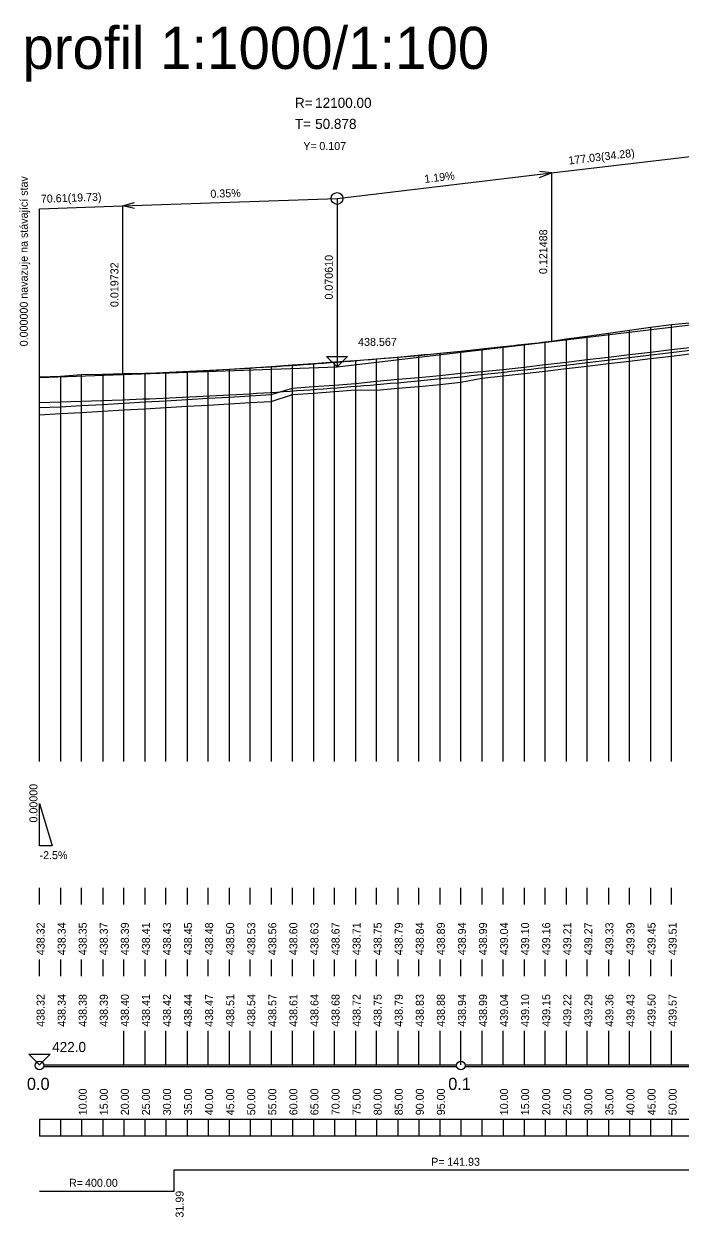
# Model space of a CAD drawing. Extents: x -240 to 1040, y 276 to 593.
# Drawn here: x 1.3 to 157, y 295.8 to 579.1 of the extents above; entities that cross this region are included whole.
import ezdxf

# ---------------------------------------------------------------- set-up
doc = ezdxf.new("R2010")
doc.units = 0
for name, color, linetype in [('1', 7, 'Continuous'), ('2', 7, 'Continuous'), ('FORMATY', 7, 'Continuous')]:
    doc.layers.add(name, color=color, linetype=linetype)

msp = doc.modelspace()

# ---------------------------------------------------------------- linework, layer by layer
at = {"layer": '1'}
for p, q in [((155, 507.67), (150, 507)), ((160, 508.13), (155, 507.67)), ((155, 404), (155, 507.67)), ((135, 504.92), (130, 504.23)), ((140, 505.62), (135, 504.92)), ((135, 404), (135, 504.92)), ((145, 506.31), (140, 505.62)), ((140, 505.62), (140, 404)), ((150, 507), (145, 506.31)), ((145, 404), (145, 506.31)), ((150, 507), (150, 404)), ((110, 501.9), (105, 501.37)), ((115, 502.43), (110, 501.9)), ((110, 501.9), (110, 404)), ((120, 502.95), (115, 502.43)), ((115, 404), (115, 502.43)), ((125, 503.51), (120, 502.95)), ((120, 502.95), (120, 404)), ((130, 504.23), (125, 503.51)), ((125, 404), (125, 503.51)), ((130, 504.23), (130, 404)), ((75, 498.78), (70, 498.43)), ((80, 499.16), (75, 498.78)), ((75, 404), (75, 498.78)), ((85, 499.54), (80, 499.16)), ((80, 499.16), (80, 404)), ((90, 499.92), (85, 499.54)), ((85, 404), (85, 499.54)), ((95, 500.31), (90, 499.92)), ((90, 499.92), (90, 404)), ((100, 500.84), (95, 500.31)), ((95, 404), (95, 500.31)), ((105, 501.37), (100, 500.84)), ((100, 500.84), (100, 404)), ((105, 404), (105, 501.37)), ((20, 495.91), (15, 495.77)), ((25, 496.03), (20, 495.91)), ((20, 495.91), (20, 404)), ((30, 496.1), (25, 496.03)), ((25, 404), (25, 496.03)), ((35, 496.18), (30, 496.1)), ((30, 496.1), (30, 404)), ((40, 496.38), (35, 496.18)), ((35, 404), (35, 496.18)), ((45, 496.71), (40, 496.38)), ((40, 496.38), (40, 404)), ((50, 497.09), (45, 496.71)), ((45, 404), (45, 496.71)), ((55, 497.41), (50, 497.09)), ((50, 497.09), (50, 404)), ((60, 497.73), (55, 497.41)), ((55, 404), (55, 497.41)), ((65, 498.07), (60, 497.73)), ((60, 497.73), (60, 404)), ((70, 498.43), (65, 498.07)), ((65, 404), (65, 498.07)), ((70, 498.43), (70, 404)), ((10, 495.42), (5, 495.22)), ((5, 404), (5, 495.22)), ((15, 495.77), (10, 495.42)), ((10, 495.42), (10, 404)), ((15, 404), (15, 495.77)), ((5, 370), (5, 374)), ((10, 374), (10, 370)), ((15, 370), (15, 374)), ((20, 374), (20, 370)), ((25, 370), (25, 374)), ((30, 374), (30, 370)), ((35, 370), (35, 374)), ((40, 374), (40, 370)), ((45, 370), (45, 374)), ((50, 374), (50, 370)), ((55, 370), (55, 374)), ((60, 374), (60, 370)), ((65, 370), (65, 374)), ((70, 374), (70, 370)), ((75, 370), (75, 374)), ((80, 374), (80, 370)), ((85, 370), (85, 374)), ((90, 374), (90, 370)), ((95, 370), (95, 374)), ((100, 374), (100, 370)), ((105, 370), (105, 374)), ((110, 374), (110, 370)), ((115, 370), (115, 374)), ((120, 374), (120, 370)), ((125, 370), (125, 374)), ((130, 374), (130, 370)), ((135, 370), (135, 374)), ((140, 374), (140, 370)), ((145, 370), (145, 374)), ((150, 374), (150, 370)), ((155, 370), (155, 374)), ((5, 353), (5, 357)), ((10, 357), (10, 353)), ((15, 353), (15, 357)), ((20, 357), (20, 353)), ((25, 353), (25, 357)), ((30, 357), (30, 353)), ((35, 353), (35, 357)), ((40, 357), (40, 353)), ((45, 353), (45, 357)), ((50, 357), (50, 353)), ((55, 353), (55, 357)), ((60, 357), (60, 353)), ((65, 353), (65, 357)), ((70, 357), (70, 353)), ((75, 353), (75, 357)), ((80, 357), (80, 353)), ((85, 353), (85, 357)), ((90, 357), (90, 353)), ((95, 353), (95, 357)), ((100, 357), (100, 353)), ((105, 353), (105, 357)), ((110, 357), (110, 353)), ((115, 353), (115, 357)), ((120, 357), (120, 353)), ((125, 353), (125, 357)), ((130, 357), (130, 353)), ((135, 353), (135, 357)), ((140, 357), (140, 353)), ((145, 353), (145, 357)), ((150, 357), (150, 353)), ((155, 353), (155, 357)), ((25, 332), (25, 340)), ((30, 340), (30, 332)), ((35, 332), (35, 340)), ((40, 340), (40, 332)), ((45, 332), (45, 340)), ((50, 340), (50, 332)), ((55, 332), (55, 340)), ((60, 340), (60, 332)), ((65, 332), (65, 340)), ((70, 340), (70, 332)), ((75, 332), (75, 340)), ((80, 340), (80, 332)), ((85, 332), (85, 340)), ((90, 340), (90, 332)), ((95, 332), (95, 340)), ((100, 340), (100, 332)), ((105, 332), (105, 340)), ((110, 340), (110, 332)), ((115, 332), (115, 340)), ((120, 340), (120, 332)), ((125, 332), (125, 340)), ((130, 340), (130, 332)), ((135, 332), (135, 340)), ((140, 340), (140, 332)), ((145, 332), (145, 340)), ((150, 340), (150, 332)), ((155, 332), (155, 340)), ((5, 332), (2.5, 334.5)), ((2.5, 334.5), (7.5, 334.5)), ((7.5, 334.5), (5, 332)), ((6, 332), (104, 332)), ((6, 331.6), (104, 331.6)), ((106, 332), (204, 332)), ((106, 331.6), (204, 331.6)), ((804.78, 319), (5, 319)), ((5, 319), (5, 315)), ((10, 319), (10, 315)), ((15, 319), (15, 315)), ((20, 319), (20, 315)), ((25, 319), (25, 315)), ((30, 319), (30, 315)), ((35, 319), (35, 315)), ((40, 319), (40, 315)), ((45, 319), (45, 315)), ((50, 319), (50, 315)), ((55, 319), (55, 315)), ((60, 319), (60, 315)), ((65, 319), (65, 315)), ((70, 319), (70, 315)), ((75, 319), (75, 315)), ((80, 319), (80, 315)), ((85, 319), (85, 315)), ((90, 319), (90, 315)), ((95, 319), (95, 315)), ((100, 319), (100, 315)), ((105, 319), (105, 315)), ((110, 319), (110, 315)), ((115, 319), (115, 315)), ((120, 319), (120, 315)), ((125, 319), (125, 315)), ((130, 319), (130, 315)), ((135, 319), (135, 315)), ((140, 319), (140, 315)), ((145, 319), (145, 315)), ((150, 319), (150, 315)), ((155, 319), (155, 315)), ((804.78, 315), (5, 315))]:
    msp.add_line(p, q, dxfattribs=at)
for centre in [(5, 331.8), (105, 331.8)]:
    msp.add_circle(centre, 1, dxfattribs=at)
at = {"layer": '2'}
for p, q in [((126.49, 543.73), (160.77, 547.81)), ((126.49, 543.73), (123.69, 544.09)), ((75.61, 537.67), (126.49, 543.73)), ((123.69, 542.69), (126.49, 543.73)), ((126.49, 543.73), (126.49, 503.73)), ((5, 535.2), (24.73, 535.89)), ((24.73, 535.89), (75.61, 537.67)), ((24.73, 535.89), (27.53, 536.69)), ((24.73, 535.89), (24.73, 495.89)), ((27.53, 535.29), (24.73, 535.89)), ((75.61, 537.67), (75.61, 497.67)), ((5, 495.2), (5, 535.2)), ((126.49, 503.73), (160.77, 507.81)), ((75.61, 497.67), (126.49, 503.73)), ((107.41, 501.61), (105.82, 501.44)), ((109, 501.77), (107.41, 501.61)), ((110.59, 501.94), (109, 501.77)), ((112.18, 502.11), (110.59, 501.94)), ((113.77, 502.28), (112.18, 502.11)), ((115.36, 502.45), (113.77, 502.28)), ((116.95, 502.63), (115.36, 502.45)), ((118.54, 502.81), (116.95, 502.63)), ((120.13, 502.99), (118.54, 502.81)), ((121.72, 503.17), (120.13, 502.99)), ((123.31, 503.35), (121.72, 503.17)), ((124.9, 503.54), (123.31, 503.35)), ((126.49, 503.73), (124.9, 503.54)), ((126.49, 497.73), (160.77, 501.81)), ((75.61, 497.67), (73.11, 500.17)), ((73.11, 500.17), (78.11, 500.17)), ((75.61, 498.74), (74.02, 498.62)), ((78.11, 500.17), (75.61, 497.67)), ((77.2, 498.86), (75.61, 498.74)), ((78.79, 498.99), (77.2, 498.86)), ((80.38, 499.12), (78.79, 498.99)), ((81.97, 499.25), (80.38, 499.12)), ((83.56, 499.38), (81.97, 499.25)), ((85.15, 499.51), (83.56, 499.38)), ((86.74, 499.65), (85.15, 499.51)), ((88.33, 499.79), (86.74, 499.65)), ((89.92, 499.93), (88.33, 499.79)), ((91.51, 500.07), (89.92, 499.93)), ((93.1, 500.21), (91.51, 500.07)), ((94.69, 500.36), (93.1, 500.21)), ((96.28, 500.51), (94.69, 500.36)), ((97.87, 500.66), (96.28, 500.51)), ((99.46, 500.81), (97.87, 500.66)), ((101.05, 500.97), (99.46, 500.81)), ((102.64, 501.12), (101.05, 500.97)), ((104.23, 501.28), (102.64, 501.12)), ((105.82, 501.44), (104.23, 501.28)), ((5, 495.2), (24.73, 495.89)), ((24.73, 495.89), (75.61, 497.67)), ((26.32, 495.95), (24.73, 495.89)), ((27.91, 496.01), (26.32, 495.95)), ((29.5, 496.07), (27.91, 496.01)), ((31.09, 496.13), (29.5, 496.07)), ((32.68, 496.19), (31.09, 496.13)), ((34.27, 496.26), (32.68, 496.19)), ((35.86, 496.33), (34.27, 496.26)), ((37.45, 496.4), (35.86, 496.33)), ((39.04, 496.48), (37.45, 496.4)), ((40.63, 496.55), (39.04, 496.48)), ((42.22, 496.63), (40.63, 496.55)), ((43.81, 496.71), (42.22, 496.63)), ((45.4, 496.79), (43.81, 496.71)), ((46.99, 496.87), (45.4, 496.79)), ((48.58, 496.96), (46.99, 496.87)), ((50.17, 497.05), (48.58, 496.96)), ((51.76, 497.14), (50.17, 497.05)), ((53.35, 497.23), (51.76, 497.14)), ((54.94, 497.32), (53.35, 497.23)), ((56.53, 497.42), (54.94, 497.32)), ((58.12, 497.52), (56.53, 497.42)), ((59.71, 497.62), (58.12, 497.52)), ((61.3, 497.72), (59.71, 497.62)), ((62.89, 497.83), (61.3, 497.72)), ((64.48, 497.93), (62.89, 497.83)), ((66.07, 498.04), (64.48, 497.93)), ((67.66, 498.15), (66.07, 498.04)), ((69.25, 498.27), (67.66, 498.15)), ((70.84, 498.38), (69.25, 498.27)), ((72.43, 498.5), (70.84, 498.38)), ((74.02, 498.62), (72.43, 498.5)), ((109, 495.77), (110.59, 495.94)), ((110.59, 495.94), (112.18, 496.11)), ((112.18, 496.11), (113.77, 496.28)), ((113.77, 496.28), (115.36, 496.45)), ((115.36, 496.45), (116.95, 496.63)), ((116.95, 496.63), (118.54, 496.81)), ((118.54, 496.81), (120.13, 496.99)), ((120.13, 496.99), (121.72, 497.17)), ((121.72, 497.17), (123.31, 497.35)), ((123.31, 497.35), (124.9, 497.54)), ((124.9, 497.54), (126.49, 497.73)), ((78.79, 492.99), (80.38, 493.12)), ((80.38, 493.12), (81.97, 493.25)), ((81.97, 493.25), (83.56, 493.38)), ((83.56, 493.38), (85.15, 493.51)), ((85.15, 493.51), (86.74, 493.65)), ((86.74, 493.65), (88.33, 493.79)), ((88.33, 493.79), (89.92, 493.93)), ((89.92, 493.93), (91.51, 494.07)), ((91.51, 494.07), (93.1, 494.21)), ((93.1, 494.21), (94.69, 494.36)), ((94.69, 494.36), (96.28, 494.51)), ((96.28, 494.51), (97.87, 494.66)), ((97.87, 494.66), (99.46, 494.81)), ((99.46, 494.81), (101.05, 494.97)), ((101.05, 494.97), (102.64, 495.12)), ((102.64, 495.12), (104.23, 495.28)), ((104.23, 495.28), (105.82, 495.44)), ((105.82, 495.44), (107.41, 495.61)), ((107.41, 495.61), (109, 495.77)), ((31.09, 490.13), (32.68, 490.19)), ((32.68, 490.19), (34.27, 490.26)), ((34.27, 490.26), (35.86, 490.33)), ((35.86, 490.33), (37.45, 490.4)), ((37.45, 490.4), (39.04, 490.48)), ((39.04, 490.48), (40.63, 490.55)), ((40.63, 490.55), (42.22, 490.63)), ((42.22, 490.63), (43.81, 490.71)), ((43.81, 490.71), (45.4, 490.79)), ((45.4, 490.79), (46.99, 490.87)), ((46.99, 490.87), (48.58, 490.96)), ((48.58, 490.96), (50.17, 491.05)), ((50.17, 491.05), (51.76, 491.14)), ((51.76, 491.14), (53.35, 491.23)), ((53.35, 491.23), (54.94, 491.32)), ((54.94, 491.32), (56.53, 491.42)), ((56.53, 491.42), (58.12, 491.52)), ((58.12, 491.52), (59.71, 491.62)), ((59.71, 491.62), (61.3, 491.72)), ((61.3, 491.72), (62.89, 491.83)), ((62.89, 491.83), (64.48, 491.93)), ((64.48, 491.93), (66.07, 492.04)), ((66.07, 492.04), (67.66, 492.15)), ((67.66, 492.15), (69.25, 492.27)), ((69.25, 492.27), (70.84, 492.38)), ((70.84, 492.38), (72.43, 492.5)), ((72.43, 492.5), (74.02, 492.62)), ((74.02, 492.62), (75.61, 492.74)), ((75.61, 492.74), (77.2, 492.86)), ((77.2, 492.86), (78.79, 492.99)), ((5, 489.2), (24.73, 489.89)), ((24.73, 489.89), (26.32, 489.95)), ((26.32, 489.95), (27.91, 490.01)), ((27.91, 490.01), (29.5, 490.07)), ((29.5, 490.07), (31.09, 490.13)), ((5, 384), (5, 394)), ((5, 394), (8, 384)), ((5, 384), (5, 394)), ((5, 394), (8, 384)), ((5, 394), (5, 394)), ((5, 394), (5, 394)), ((5, 389), (5, 389)), ((8, 384), (5, 384)), ((8, 384), (5, 384)), ((5, 384), (5, 384)), ((5, 384), (5, 384)), ((36.99, 302), (36.99, 307)), ((36.99, 307), (178.92, 307)), ((5, 302), (36.99, 302))]:
    msp.add_line(p, q, dxfattribs=at)
for points in [[(5, 488.07), (10, 488.19), (15, 488.48), (20, 488.77), (25, 489.06), (30, 489.35), (35, 489.65), (40, 489.94), (45, 490.23), (50, 490.52), (55, 490.81), (60, 491.1), (65, 492.64), (70, 492.99), (75, 493.37), (80, 493.77), (85, 494.3), (90, 494.73), (95, 495.19), (100, 495.66), (105, 496.16), (110, 496.56), (115, 497.09), (120, 497.65), (125, 498.23), (130, 498.82), (135, 499.42), (140, 500.01), (145, 500.61), (150, 501.2), (155, 501.8), (160, 502.39)], [(5, 486.3), (9.98, 486.59), (15, 486.88), (20, 487.17), (25, 487.46), (30, 487.75), (35, 488.05), (40, 488.34), (45, 488.63), (50, 488.92), (55, 489.21), (60, 489.5), (65, 491.11), (70, 491.46), (75, 491.83), (80, 492.2), (85, 492.16), (90, 492.6), (95, 493.05), (100, 493.53), (105, 494.02), (110, 494.99), (115, 495.56), (120, 496.11), (125, 496.69), (130, 497.29), (135, 497.88), (140, 498.48), (145, 499.07), (150, 499.67), (155, 500.26), (160, 500.86)]]:
    msp.add_lwpolyline(points, dxfattribs=at)
msp.add_circle((75.61, 537.67), 1.4, dxfattribs=at)

# ---------------------------------------------------------------- texts
at = {"layer": '1'}
for s, p in [('438.32', (6.2, 341)), ('438.34', (11.2, 341)), ('438.38', (16.2, 341)), ('438.39', (21.2, 341)), ('438.40', (26.2, 341)), ('438.41', (31.2, 341)), ('438.42', (36.2, 341)), ('438.44', (41.2, 341)), ('438.47', (46.2, 341)), ('438.51', (51.2, 341)), ('438.54', (56.2, 341)), ('438.57', (61.2, 341)), ('438.61', (66.2, 341)), ('438.64', (71.2, 341)), ('438.68', (76.2, 341)), ('438.72', (81.2, 341)), ('438.75', (86.2, 341)), ('438.79', (91.2, 341)), ('438.83', (96.2, 341)), ('438.88', (101.2, 341)), ('438.94', (106.2, 341)), ('438.99', (111.2, 341)), ('439.04', (116.2, 341)), ('439.10', (121.2, 341)), ('439.15', (126.2, 341)), ('439.22', (131.2, 341)), ('439.29', (136.2, 341)), ('439.36', (141.2, 341)), ('439.43', (146.2, 341)), ('439.50', (151.2, 341)), ('439.57', (156.2, 341)), ('10.00', (16.2, 320)), ('15.00', (21.2, 320)), ('20.00', (26.2, 320)), ('25.00', (31.2, 320)), ('30.00', (36.2, 320)), ('35.00', (41.2, 320)), ('40.00', (46.2, 320)), ('45.00', (51.2, 320)), ('50.00', (56.2, 320)), ('55.00', (61.2, 320)), ('60.00', (66.2, 320)), ('65.00', (71.2, 320)), ('70.00', (76.2, 320)), ('75.00', (81.2, 320)), ('80.00', (86.2, 320)), ('85.00', (91.2, 320)), ('90.00', (96.2, 320)), ('95.00', (101.2, 320)), ('10.00', (116.2, 320)), ('15.00', (121.2, 320)), ('20.00', (126.2, 320)), ('25.00', (131.2, 320)), ('30.00', (136.2, 320)), ('35.00', (141.2, 320)), ('40.00', (146.2, 320)), ('45.00', (151.2, 320)), ('50.00', (156.2, 320))]:
    msp.add_text(s, height=1.9, rotation=90, dxfattribs=at).set_placement(p)
for s, height, p in [('422.0', 2.4, (8, 335)), ('0.0', 2.9, (2, 326)), ('0.1', 2.9, (102, 326))]:
    msp.add_text(s, height=height, dxfattribs=at).set_placement(p)
at = {"layer": '2'}
for s, height, p in [('R=', 2.4, (65.61, 559.18)), ('12100.00', 2.4, (70.41, 559.18)), ('T=', 2.4, (65.61, 554.18)), ('50.878', 2.4, (70.41, 554.18)), ('Y=', 1.9, (67.61, 549.18)), ('0.107', 1.9, (71.41, 549.18)), ('438.567', 1.9, (80.61, 502.67)), ('-2.5%', 1.9, (5, 380.8)), ('-2.5%', 1.9, (5, 380.8)), ('P=', 1.9, (97.96, 308)), ('141.93', 1.9, (101.76, 308)), ('R=', 1.9, (12, 303)), ('400.00', 1.9, (15.8, 303))]:
    msp.add_text(s, height=height, dxfattribs=at).set_placement(p)
for s, rotation, p in [('177.03(34.28)', 6.7905, (130.63, 545.72)), ('  1.19%', 6.7905, (95.05, 541.18)), ('0.000000 navazuje na stávající stav', 90, (2.21, 502.57)), ('70.61(19.73)', 2.0033, (5.34, 536.63)), ('  0.35%', 2.0033, (44.17, 537.77)), ('0.121488', 90, (125.49, 519.73)), ('0.070610', 90, (74.61, 513.67)), ('0.019732', 90, (23.73, 511.89)), ('0.00000', 90, (4.5, 389.5)), ('0.00000', 90, (4.5, 389.5)), ('438.32', 90, (6.2, 358)), ('438.34', 90, (11.2, 358)), ('438.35', 90, (16.2, 358)), ('438.37', 90, (21.2, 358)), ('438.39', 90, (26.2, 358)), ('438.41', 90, (31.2, 358)), ('438.43', 90, (36.2, 358)), ('438.45', 90, (41.2, 358)), ('438.48', 90, (46.2, 358)), ('438.50', 90, (51.2, 358)), ('438.53', 90, (56.2, 358)), ('438.56', 90, (61.2, 358)), ('438.60', 90, (66.2, 358)), ('438.63', 90, (71.2, 358)), ('438.67', 90, (76.2, 358)), ('438.71', 90, (81.2, 358)), ('438.75', 90, (86.2, 358)), ('438.79', 90, (91.2, 358)), ('438.84', 90, (96.2, 358)), ('438.89', 90, (101.2, 358)), ('438.94', 90, (106.2, 358)), ('438.99', 90, (111.2, 358)), ('439.04', 90, (116.2, 358)), ('439.10', 90, (121.2, 358)), ('439.16', 90, (126.2, 358)), ('439.21', 90, (131.2, 358)), ('439.27', 90, (136.2, 358)), ('439.33', 90, (141.2, 358)), ('439.39', 90, (146.2, 358)), ('439.45', 90, (151.2, 358)), ('439.51', 90, (156.2, 358)), (' 31.99', 90, (39.19, 295))]:
    msp.add_text(s, height=1.9, rotation=rotation, dxfattribs=at).set_placement(p)
at = {"layer": 'FORMATY'}
msp.add_text('Podélný profil 1:1000/1:100', height=10, dxfattribs=at).set_placement((-51.1, 568.43))

doc.saveas('drawing.dxf')
